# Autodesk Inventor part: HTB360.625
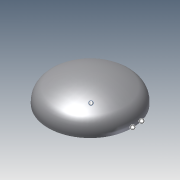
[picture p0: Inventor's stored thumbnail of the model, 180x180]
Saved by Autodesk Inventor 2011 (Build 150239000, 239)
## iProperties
Created: 2010-05
Part Number: HTB360.625
Document SubType Name: Modeling
Designer: mklassen
Density: 1 g/cm^3
Description: HEAD TORISPHERICAL 0.8 36"x 0.625"
THK: 0.625 in
OD: 36.000 in
LIP: 1.000 in
DRFAC: 0.850 ul
KRFAC: 0.154 ul
Author: mklassen
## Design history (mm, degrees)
sketch "skConical"
  geometry: L1 (0, -141.168)-(0, 847.008) reference; L2 (-135.363, 0)-(563.935, 0) reference; L3 (441.325, 0)-(441.325, 25.4); L4 (416.166, 105.729)-(20.862, 674.889); L5 (0, 685.8)-(-35.463, 685.8); L6 (33.901, 683.945)-(429.204, 114.785); L7 (457.2, 25.4)-(457.2, 0); L8 (441.325, 0)-(457.2, 0); L9 (0, 685.8)-(0, 701.675); A1 r 140.818 centre (300.507, 25.4) between (441.325, 25.4) and (416.166, 105.729); A2 r 25.4 centre (0, 660.4) between (20.862, 674.889) and (0, 685.8); A3 r 41.275 centre (0, 660.4) between (33.901, 683.945) and (0, 701.675); A4 r 156.693 centre (300.507, 25.4) between (457.2, 25.4) and (429.204, 114.785); 1 further point
  constraints: 14 end point, 8 point on circle, 4 centre point, 4 tangent, 2 perpendicular, 2 point on line, 1 collinear, 1 horizontal, 3 other
  dimensions: "d6" = 140.8176 radius of A1 (derived); "d7" = 15.875 distance between parallel lines of L7 L3 (derived); "d8" = 25.4 distance of L3.start L3.end (= LIP); "d9" = 914.4 diameter of L7 L1 (derived); "d10" = 685.8 distance between parallel lines of L5 L2 (derived); "d11" = 25.4 radius of A2
revolve "Conical" sketch "skConical" stored, may be unused: angle "d12" = 90 deg
sketch "skDiffuser"
  geometry: L1 (0, -418.496)-(0, 724.257) reference; L2 (-95.259, 0)-(571.555, 0) reference; L3 (441.325, 0)-(441.325, 142.234); L4 (441.325, 0)-(457.2, 0); L5 (0, -216.233)-(0, -232.108); A1 r 140.818 centre (300.507, 0) between (366.999, -124.131) and (441.325, 0); A2 r 777.24 centre (0, 561.007) between (0, -216.233) and (366.999, -124.131); A3 r 793.115 centre (0, 561.007) between (0, -232.108) and (374.495, -138.125); A4 r 156.693 centre (300.507, 0) between (374.495, -138.125) and (457.2, 0); 1 further point
  constraints: 8 point on circle, 6 end point, 4 centre point, 3 point on line, 2 perpendicular, 2 tangent, 1 collinear, 1 other
  dimensions: "d15" = 140.8176 radius of A1 (derived); "d16" = 777.24 radius of A2 (derived); "d17" = 15.875 distance of L3.start L4.end (derived); "d18" = 914.4 diameter of L4.end L1 (derived)
revolve "Diffuser" sketch "skDiffuser" stored, may be unused: angle "d19" = 90 deg
sketch "skEllipsoidal"
  geometry: L1 (-110.32, 0)-(595.975, 0) reference; L2 (0, -64.258)-(0, 365.786) reference; L3 (441.325, 0)-(457.2, 0); L4 (0, 212.725)-(0, 228.6); 2 further points; 1 other entity
  constraints: 4 end point, 2 point on line, 1 coincident, 1 collinear, 1 horizontal, 1 perpendicular, 7 other
  dimensions: "d22" = 914.4 diameter of L3.end L2 (derived); "d23" = 228.6 distance from line of L4.end L1 (derived); "d24" = 15.875 distance of L3.start L3.end (derived)
revolve "Ellipsoidal" sketch "skEllipsoidal" stored, may be unused: angle "d25" = 90 deg
sketch "skFlat"
  geometry: L1 (-97.93, 0)-(587.583, 0) reference; L2 (0, -42.909)-(0, 257.454) reference; L3 (457.2, 0)-(457.2, 25.4); L4 (300.507, 182.093)-(0, 182.093); L5 (0, 166.218)-(300.507, 166.218); L6 (441.325, 25.4)-(441.325, 0); L7 (0, 166.218)-(0, 182.093); L8 (441.325, 0)-(457.2, 0); A1 r 156.693 centre (300.507, 25.4) between (457.2, 25.4) and (300.507, 182.093); A2 r 140.818 centre (300.507, 25.4) between (441.325, 25.4) and (300.507, 166.218); 1 further point
  constraints: 12 end point, 4 point on circle, 2 centre point, 2 perpendicular, 2 point on line, 2 tangent, 1 collinear, 1 parallel, 2 other
  dimensions: "d28" = 914.4 diameter of L3 L2 (derived); "d31" = 140.8176 radius of A2 (derived); "d32" = 15.875 distance of L6.end L3.start (derived); "d33" = 25.4 distance of L6.start L6.end (= LIP)
revolve "Flat" sketch "skFlat" stored, may be unused: angle "d34" = 90 deg
sketch "skHemispherical"
  geometry: L1 (0, -110.378)-(0, 662.267) reference; L2 (-110.378, 0)-(662.267, 0) reference; L3 (441.325, 0)-(457.2, 0); L4 (0, 441.325)-(0, 457.2); A1 r 457.2 centre (0, 0) between (457.2, 0) and (0, 457.2); A2 r 441.325 centre (0, 0) between (441.325, 0) and (0, 441.325); 1 further point
  constraints: 5 point on circle, 4 end point, 2 centre point, 2 collinear, 2 point on line, 1 coincident
  dimensions: "d37" = 914.4 diameter of L3.end L1 (derived); "d38" = 15.875 distance of L3.start L3.end (derived)
revolve "Hemispherical" sketch "skHemispherical" stored, may be unused: angle "d39" = 90 deg
sketch "skTorispherical"
  geometry: L1 (-95.259, 0)-(571.555, 0) reference; L2 (0, -698.857)-(0, 443.896) reference; L3 (441.325, 0)-(441.325, 25.4); L4 (457.2, 25.4)-(457.2, 0); L5 (441.325, 0)-(457.2, 0); L6 (0, 241.633)-(0, 257.508); A1 r 140.818 centre (300.507, 25.4) between (441.325, 25.4) and (366.999, 149.531); A2 r 777.24 centre (0, -535.607) between (366.999, 149.531) and (0, 241.633); A3 r 793.115 centre (0, -535.607) between (374.495, 163.525) and (0, 257.508); A4 r 156.693 centre (300.507, 25.4) between (457.2, 25.4) and (374.495, 163.525); 1 further point
  constraints: 8 end point, 8 point on circle, 4 centre point, 2 perpendicular, 2 point on line, 2 tangent, 1 collinear, 1 vertical alignment, 2 other
  dimensions: "d43" = 25.4 distance of L3.start L3.end (= LIP); "d44" = 140.8176 radius of A1 (derived); "d45" = 777.24 radius of A2 (derived); "d46" = 15.875 distance of L3.start L4.end (derived); "d47" = 914.4 diameter of L4 L2 (derived)
revolve "Torispherical" sketch "skTorispherical" stored, may be unused: angle "d48" = 90 deg
body "Solid1"
other parameters: "LIP" = 25.4 [user parameter; used in 3 equation terms], "DRFAC" = 0.85 [user parameter; used in 2 equation terms], "KRFAC" = 0.154 [user parameter; used in 4 equation terms], "d13" = 0, "d14" = 0, "d20" = 0, "d21" = 0, "d26" = 0, "d27" = 0, "d35" = 0, "d36" = 0, "d40" = 0, "d41" = 0, "d49" = 0, "d50" = 0, "d51" = 0, "d52" = 0
